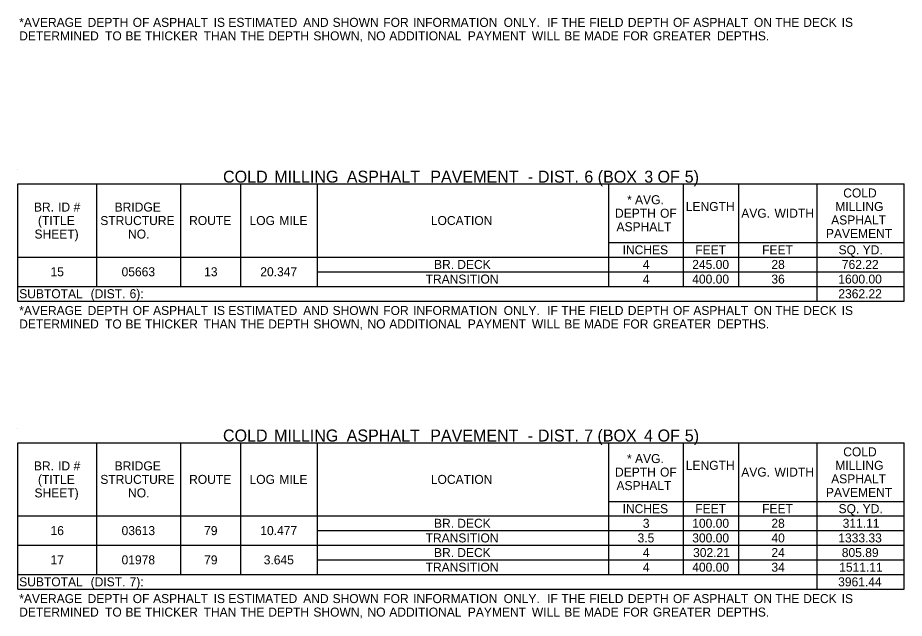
# Model space of a CAD drawing. Extents: x 544255 to 1930787, y -1947044 to 596640.
# Drawn here: x 553844 to 554435, y -1946985 to -1946584 of the extents above; entities that cross this region are included whole.
import ezdxf

# ---------------------------------------------------------------- set-up
doc = ezdxf.new("R2010")
doc.units = 0
doc.layers.add('Default', color=7, linetype='Continuous')

msp = doc.modelspace()

# ---------------------------------------------------------------- linework, layer by layer
at = {"layer": 'Default'}
for p, q in [((553844, -1946685.39), (553844, -1946685.39)), ((553844, -1946695.14), (554434.85, -1946695.14)), ((553844, -1946695.14), (554434.85, -1946695.14)), ((553844, -1946773.14), (553844, -1946695.14)), ((553896.65, -1946763.39), (553896.65, -1946695.14)), ((553952.71, -1946763.39), (553952.71, -1946695.14)), ((553992.69, -1946763.39), (553992.69, -1946695.14)), ((554043.87, -1946763.39), (554043.87, -1946695.14)), ((554237.9, -1946763.39), (554237.9, -1946695.14)), ((554287.62, -1946763.39), (554287.62, -1946695.14)), ((554324.67, -1946763.39), (554324.67, -1946695.14)), ((554376.84, -1946773.14), (554376.84, -1946695.14)), ((554434.85, -1946773.14), (554434.85, -1946695.14)), ((554237.9, -1946734.14), (554324.67, -1946734.14)), ((554237.9, -1946734.14), (554287.62, -1946734.14)), ((554287.62, -1946734.14), (554434.85, -1946734.14)), ((554324.67, -1946743.89), (554324.67, -1946734.14)), ((553844, -1946743.89), (554434.85, -1946743.89)), ((554043.87, -1946753.64), (554434.85, -1946753.64)), ((553844, -1946763.39), (554043.87, -1946763.39)), ((553844, -1946763.39), (554434.85, -1946763.39)), ((554043.87, -1946763.39), (554434.85, -1946763.39)), ((553844, -1946773.14), (554434.85, -1946773.14)), ((553844, -1946857.89), (553844, -1946857.89)), ((553844, -1946867.64), (554434.85, -1946867.64)), ((553844, -1946867.64), (554434.85, -1946867.64)), ((553844, -1946965.14), (553844, -1946867.64)), ((553896.65, -1946955.39), (553896.65, -1946867.64)), ((553952.71, -1946955.39), (553952.71, -1946867.64)), ((553992.69, -1946955.39), (553992.69, -1946867.64)), ((554043.87, -1946955.39), (554043.87, -1946867.64)), ((554237.9, -1946955.39), (554237.9, -1946867.64)), ((554287.62, -1946955.39), (554287.62, -1946867.64)), ((554324.67, -1946955.39), (554324.67, -1946867.64)), ((554376.84, -1946965.14), (554376.84, -1946867.64)), ((554434.85, -1946965.14), (554434.85, -1946867.64)), ((554237.9, -1946906.64), (554324.67, -1946906.64)), ((554237.9, -1946906.64), (554287.62, -1946906.64)), ((554287.62, -1946906.64), (554434.85, -1946906.64)), ((554324.67, -1946916.39), (554324.67, -1946906.64)), ((553844, -1946916.39), (554434.85, -1946916.39)), ((554043.87, -1946926.14), (554434.85, -1946926.14)), ((553844, -1946935.89), (554043.87, -1946935.89)), ((553844, -1946935.89), (554434.85, -1946935.89)), ((554043.87, -1946935.89), (554434.85, -1946935.89)), ((554043.87, -1946945.64), (554434.85, -1946945.64)), ((553844, -1946955.39), (554043.87, -1946955.39)), ((553844, -1946955.39), (554434.85, -1946955.39)), ((554043.87, -1946955.39), (554434.85, -1946955.39)), ((553844, -1946965.14), (554434.85, -1946965.14))]:
    msp.add_line(p, q, dxfattribs=at)

# ---------------------------------------------------------------- texts
for s, height, p in [('*AVERAGE', 6, (553844.97, -1946590.44)), (' DEPTH', 6, (553888.33, -1946590.44)), (' OF', 6, (553918.4, -1946590.44)), (' ASPHALT', 6, (553931.98, -1946590.44)), (' IS', 6, (553972.35, -1946590.44)), (' ESTIMATED', 6, (553982.16, -1946590.44)), (' AND', 6, (554032.02, -1946590.44)), (' SHOWN', 6, (554051.6, -1946590.44)), (' FOR', 6, (554085.38, -1946590.44)), (' INFORMATION', 6, (554105.29, -1946590.44)), (' ONLY.', 6, (554165.62, -1946590.44)), ('  IF', 6, (554192.37, -1946590.44)), (' THE', 6, (554204.09, -1946590.44)), (' FIELD', 6, (554222.74, -1946590.44)), (' DEPTH', 6, (554248.38, -1946590.44)), (' OF', 6, (554278.45, -1946590.44)), (' ASPHALT', 6, (554292.03, -1946590.44)), (' ON', 6, (554332.4, -1946590.44)), (' THE', 6, (554346.62, -1946590.44)), (' DECK', 6, (554365.27, -1946590.44)), (' IS', 6, (554390.87, -1946590.44)), ('DETERMINED', 6, (553844.97, -1946599.44)), (' TO', 6, (553899.96, -1946599.44)), (' BE', 6, (553913.55, -1946599.44)), (' THICKER', 6, (553926.62, -1946599.44)), (' THAN', 6, (553965.63, -1946599.44)), (' THE', 6, (553990.1, -1946599.44)), (' DEPTH', 6, (554008.75, -1946599.44)), (' SHOWN,', 6, (554038.82, -1946599.44)), (' NO', 6, (554074.86, -1946599.44)), (' ADDITIONAL', 6, (554089.39, -1946599.44)), (' PAYMENT', 6, (554141.73, -1946599.44)), (' WILL', 6, (554184.42, -1946599.44)), (' BE', 6, (554206.01, -1946599.44)), (' MADE', 6, (554219.08, -1946599.44)), (' FOR', 6, (554245.18, -1946599.44)), (' GREATER', 6, (554265.09, -1946599.44)), (' DEPTHS.', 6, (554307.84, -1946599.44)), ('COLD', 8, (553980.85, -1946694.27)), (' MILLING', 8, (554011.97, -1946694.27)), (' ASPHALT', 8, (554060.34, -1946694.27)), (' PAVEMENT', 8, (554116, -1946694.27)), (' -', 8, (554180.99, -1946694.27)), (' DIST.', 8, (554187.73, -1946694.27)), (' 6', 8, (554218.64, -1946694.27)), (' (BOX', 8, (554227.56, -1946694.27)), (' 3', 8, (554258.59, -1946694.27)), (' OF', 8, (554267.43, -1946694.27)), (' 5)', 8, (554285.54, -1946694.27)), ('*', 6, (554250.1, -1946708.64)), (' AVG.', 6, (554253.18, -1946708.64)), ('COLD', 6, (554394.17, -1946704.14)), ('BR.', 6, (553854.8, -1946713.52)), (' ID', 6, (553868.66, -1946713.52)), (' #', 6, (553878.96, -1946713.52)), ('BRIDGE', 6, (553908.58, -1946713.52)), ('LENGTH', 6, (554289.24, -1946713.14)), ('MILLING', 6, (554388.87, -1946713.14)), ('DEPTH', 6, (554242.08, -1946717.64)), (' OF', 6, (554269.86, -1946717.64)), ('AVG.', 6, (554326.22, -1946717.64)), (' WIDTH', 6, (554346.14, -1946717.64)), ('(TITLE', 6, (553857.49, -1946722.52)), ('STRUCTURE', 6, (553899.04, -1946722.52)), ('ROUTE', 6, (553958.23, -1946722.52)), ('LOG', 6, (553998.48, -1946722.52)), (' MILE', 6, (554016.14, -1946722.52)), ('LOCATION', 6, (554119.33, -1946722.52)), ('ASPHALT', 6, (554243.05, -1946726.64)), ('ASPHALT', 6, (554386.13, -1946722.14)), ('SHEET)', 6, (553855.17, -1946731.52)), ('NO.', 6, (553917.52, -1946731.52)), ('PAVEMENT', 6, (554382.64, -1946731.14)), ('INCHES', 6, (554247.13, -1946742.02)), ('FEET', 6, (554295.52, -1946742.02)), ('FEET', 6, (554340.13, -1946742.02)), ('SQ.', 6, (554391.05, -1946742.02)), (' YD.', 6, (554404.91, -1946742.02)), ('BR.', 6, (554121.46, -1946751.77)), (' DECK', 6, (554134.71, -1946751.77)), ('4', 6, (554260.63, -1946751.77)), ('245.00', 6, (554293.54, -1946751.77)), ('28', 6, (554346.28, -1946751.77)), ('762.22', 6, (554393.25, -1946751.77)), ('15', 6, (553865.83, -1946756.64)), ('05663', 6, (553913.22, -1946756.64)), ('13', 6, (553968.23, -1946756.64)), ('20.347', 6, (554005.66, -1946756.64)), ('TRANSITION', 6, (554115.84, -1946761.52)), ('4', 6, (554260.63, -1946761.52)), ('400.00', 6, (554293.54, -1946761.52)), ('36', 6, (554346.28, -1946761.52)), ('1600.00', 6, (554390.9, -1946761.52)), ('SUBTOTAL', 6, (553844.97, -1946771.27)), (' (DIST.', 6, (553890.37, -1946771.27)), (' 6):', 6, (553916.33, -1946771.27)), ('2362.22', 6, (554390.91, -1946771.27)), ('*AVERAGE', 6, (553844.97, -1946782.44)), (' DEPTH', 6, (553888.33, -1946782.44)), (' OF', 6, (553918.4, -1946782.44)), (' ASPHALT', 6, (553931.98, -1946782.44)), (' IS', 6, (553972.35, -1946782.44)), (' ESTIMATED', 6, (553982.16, -1946782.44)), (' AND', 6, (554032.02, -1946782.44)), (' SHOWN', 6, (554051.6, -1946782.44)), (' FOR', 6, (554085.38, -1946782.44)), (' INFORMATION', 6, (554105.29, -1946782.44)), (' ONLY.', 6, (554165.62, -1946782.44)), ('  IF', 6, (554192.37, -1946782.44)), (' THE', 6, (554204.09, -1946782.44)), (' FIELD', 6, (554222.74, -1946782.44)), (' DEPTH', 6, (554248.38, -1946782.44)), (' OF', 6, (554278.45, -1946782.44)), (' ASPHALT', 6, (554292.03, -1946782.44)), (' ON', 6, (554332.4, -1946782.44)), (' THE', 6, (554346.62, -1946782.44)), (' DECK', 6, (554365.27, -1946782.44)), (' IS', 6, (554390.87, -1946782.44)), ('DETERMINED', 6, (553844.97, -1946791.44)), (' TO', 6, (553899.96, -1946791.44)), (' BE', 6, (553913.55, -1946791.44)), (' THICKER', 6, (553926.62, -1946791.44)), (' THAN', 6, (553965.63, -1946791.44)), (' THE', 6, (553990.1, -1946791.44)), (' DEPTH', 6, (554008.75, -1946791.44)), (' SHOWN,', 6, (554038.82, -1946791.44)), (' NO', 6, (554074.86, -1946791.44)), (' ADDITIONAL', 6, (554089.39, -1946791.44)), (' PAYMENT', 6, (554141.73, -1946791.44)), (' WILL', 6, (554184.42, -1946791.44)), (' BE', 6, (554206.01, -1946791.44)), (' MADE', 6, (554219.08, -1946791.44)), (' FOR', 6, (554245.18, -1946791.44)), (' GREATER', 6, (554265.09, -1946791.44)), (' DEPTHS.', 6, (554307.84, -1946791.44)), ('COLD', 8, (553980.79, -1946866.77)), (' MILLING', 8, (554011.9, -1946866.77)), (' ASPHALT', 8, (554060.27, -1946866.77)), (' PAVEMENT', 8, (554115.94, -1946866.77)), (' DIST.', 8, (554187.67, -1946866.77)), (' 7', 8, (554218.57, -1946866.77)), (' (BOX', 8, (554227.4, -1946866.77)), (' 4', 8, (554258.43, -1946866.77)), (' OF', 8, (554267.49, -1946866.77)), (' 5)', 8, (554285.6, -1946866.77)), (' -', 8, (554180.93, -1946866.77)), ('COLD', 6, (554394.17, -1946876.64)), ('BR.', 6, (553854.8, -1946886.02)), (' ID', 6, (553868.66, -1946886.02)), (' #', 6, (553878.96, -1946886.02)), ('BRIDGE', 6, (553908.58, -1946886.02)), ('*', 6, (554250.1, -1946881.14)), (' AVG.', 6, (554253.18, -1946881.14)), ('LENGTH', 6, (554289.24, -1946885.64)), ('MILLING', 6, (554388.87, -1946885.64)), ('DEPTH', 6, (554242.08, -1946890.14)), (' OF', 6, (554269.86, -1946890.14)), ('AVG.', 6, (554326.22, -1946890.14)), (' WIDTH', 6, (554346.14, -1946890.14)), ('(TITLE', 6, (553857.49, -1946895.02)), ('STRUCTURE', 6, (553899.04, -1946895.02)), ('ROUTE', 6, (553958.23, -1946895.02)), ('LOG', 6, (553998.48, -1946895.02)), (' MILE', 6, (554016.14, -1946895.02)), ('LOCATION', 6, (554119.33, -1946895.02)), ('ASPHALT', 6, (554386.13, -1946894.64)), ('SHEET)', 6, (553855.17, -1946904.02)), ('NO.', 6, (553917.52, -1946904.02)), ('ASPHALT', 6, (554243.05, -1946899.14)), ('PAVEMENT', 6, (554382.64, -1946903.64)), ('INCHES', 6, (554247.13, -1946914.52)), ('FEET', 6, (554295.52, -1946914.52)), ('FEET', 6, (554340.13, -1946914.52)), ('SQ.', 6, (554391.05, -1946914.52)), (' YD.', 6, (554404.91, -1946914.52)), ('BR.', 6, (554121.46, -1946924.27)), (' DECK', 6, (554134.71, -1946924.27)), ('3', 6, (554260.62, -1946924.27)), ('100.00', 6, (554293.54, -1946924.27)), ('28', 6, (554346.28, -1946924.27)), ('311.11', 6, (554393.8, -1946924.27)), ('16', 6, (553865.85, -1946929.14)), ('03613', 6, (553913.22, -1946929.14)), ('79', 6, (553968.22, -1946929.14)), ('10.477', 6, (554005.66, -1946929.14)), ('TRANSITION', 6, (554115.84, -1946934.02)), ('3.5', 6, (554257.1, -1946934.02)), ('300.00', 6, (554293.54, -1946934.02)), ('40', 6, (554346.3, -1946934.02)), ('1333.33', 6, (554390.89, -1946934.02)), ('BR.', 6, (554121.46, -1946943.77)), (' DECK', 6, (554134.71, -1946943.77)), ('4', 6, (554260.63, -1946943.77)), ('302.21', 6, (554294.1, -1946943.77)), ('24', 6, (554346.3, -1946943.77)), ('805.89', 6, (554393.21, -1946943.77)), ('17', 6, (553865.85, -1946948.64)), ('01978', 6, (553913.21, -1946948.64)), ('79', 6, (553968.22, -1946948.64)), ('3.645', 6, (554007.96, -1946948.64)), ('TRANSITION', 6, (554115.84, -1946953.52)), ('4', 6, (554260.63, -1946953.52)), ('400.00', 6, (554293.54, -1946953.52)), ('34', 6, (554346.3, -1946953.52)), ('1511.11', 6, (554391.47, -1946953.52)), (' (DIST.', 6, (553890.37, -1946963.27)), (' 7):', 6, (553916.33, -1946963.27)), ('SUBTOTAL', 6, (553844.97, -1946963.27)), ('3961.44', 6, (554390.79, -1946963.27)), ('*AVERAGE', 6, (553844.97, -1946974.44)), (' DEPTH', 6, (553888.33, -1946974.44)), (' OF', 6, (553918.4, -1946974.44)), (' ASPHALT', 6, (553931.98, -1946974.44)), (' IS', 6, (553972.35, -1946974.44)), (' ESTIMATED', 6, (553982.16, -1946974.44)), (' AND', 6, (554032.02, -1946974.44)), (' SHOWN', 6, (554051.6, -1946974.44)), (' FOR', 6, (554085.38, -1946974.44)), (' INFORMATION', 6, (554105.29, -1946974.44)), (' ONLY.', 6, (554165.62, -1946974.44)), ('  IF', 6, (554192.37, -1946974.44)), (' THE', 6, (554204.09, -1946974.44)), (' FIELD', 6, (554222.74, -1946974.44)), (' DEPTH', 6, (554248.38, -1946974.44)), (' OF', 6, (554278.45, -1946974.44)), (' ASPHALT', 6, (554292.03, -1946974.44)), (' ON', 6, (554332.4, -1946974.44)), (' THE', 6, (554346.62, -1946974.44)), (' DECK', 6, (554365.27, -1946974.44)), (' IS', 6, (554390.87, -1946974.44)), ('DETERMINED', 6, (553844.97, -1946983.44)), (' TO', 6, (553899.96, -1946983.44)), (' BE', 6, (553913.55, -1946983.44)), (' THICKER', 6, (553926.62, -1946983.44)), (' THAN', 6, (553965.63, -1946983.44)), (' THE', 6, (553990.1, -1946983.44)), (' DEPTH', 6, (554008.75, -1946983.44)), (' SHOWN,', 6, (554038.82, -1946983.44)), (' NO', 6, (554074.86, -1946983.44)), (' ADDITIONAL', 6, (554089.39, -1946983.44)), (' PAYMENT', 6, (554141.73, -1946983.44)), (' WILL', 6, (554184.42, -1946983.44)), (' BE', 6, (554206.01, -1946983.44)), (' MADE', 6, (554219.08, -1946983.44)), (' FOR', 6, (554245.18, -1946983.44)), (' GREATER', 6, (554265.09, -1946983.44)), (' DEPTHS.', 6, (554307.84, -1946983.44))]:
    msp.add_text(s, height=height, dxfattribs=at).set_placement(p)

doc.saveas('drawing.dxf')
